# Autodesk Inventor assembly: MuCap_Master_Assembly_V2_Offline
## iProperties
Shininess: 64.0
Length Units: 11269
Angle Units: 11279
Time Units: 11290
Mass Units: 11283
Length Display Precision: 3
Angle Display Precision: 2
Compacted: True
Created: 2004-08
Part Number: MuCap_Master_Assembly_V2_Offline
Document SubType Name: Assembly
Designer: John Blackburn
Manufacturer: Standard
Standards Organization: Custom
Density: 0.0
Volumn: 0.0
Area: 0.0
PropertySet Name: Model Information
Control State: 0
Master: False
Checked Out: False
Author: John Blackburn
